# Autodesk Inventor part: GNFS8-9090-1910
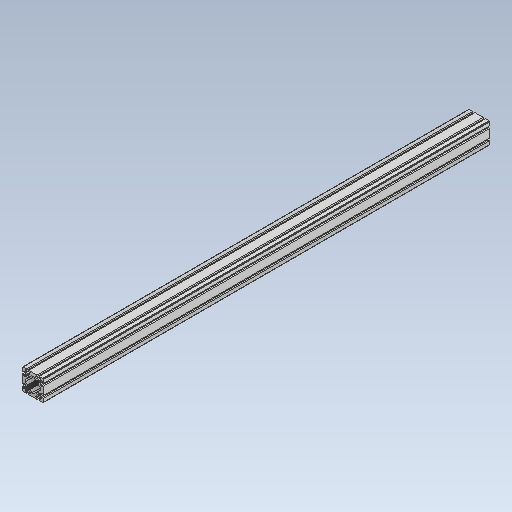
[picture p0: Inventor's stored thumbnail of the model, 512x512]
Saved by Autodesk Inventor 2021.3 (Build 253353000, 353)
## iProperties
Created: 2022-02
Part Number: GNFS8-9090-1910
Material: 一般
Document SubType Name: Modeling
Designer: kengo
Density: 1 g/cm^3
Appearance: 既定
Author: kengo
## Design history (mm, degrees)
feature "GNFS8-9090-1910"
node "ソリッド1"
